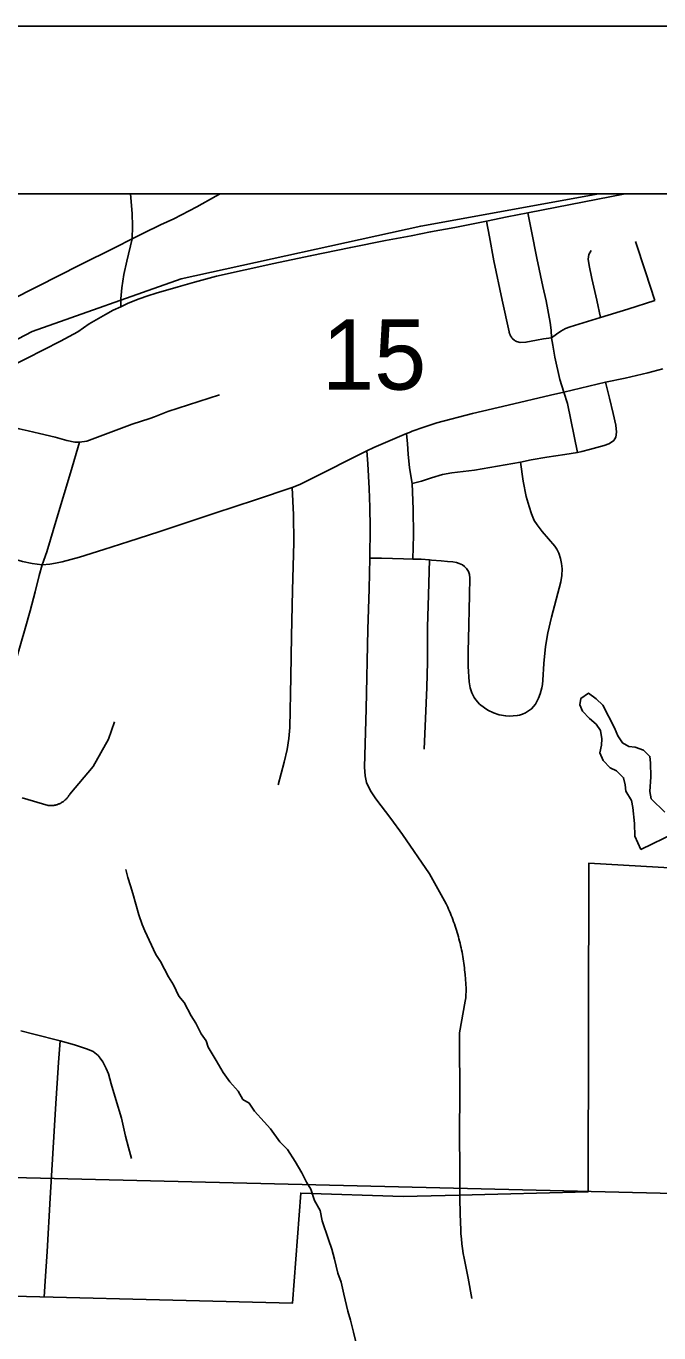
# Model space of a CAD drawing. Extents: x -7.9 to 76.1, y 0 to 22.
# Drawn here: x 2.741 to 3.119, y 20.221 to 21 of the extents above; entities that cross this region are included whole.
import ezdxf

# ---------------------------------------------------------------- set-up
doc = ezdxf.new("R2010")
doc.units = 0
for name, color, linetype in [('GM_X_City_Street', 7, 'Continuous'), ('GM_X_Corporation', 7, 'Continuous'), ('GM_X_County_Road', 7, 'Continuous'), ('GM_X_Minor_River', 7, 'Continuous'), ('GM_X_Rail_Line', 7, 'Continuous'), ('GM_X_Section', 7, 'Continuous'), ('GM_X_Section_Text', 7, 'Continuous'), ('GM_X_State_Route', 7, 'Continuous'), ('GM_X_Township_Road', 7, 'Continuous'), ('SC_Scratch1', 7, 'Continuous'), ('SH_Data', 7, 'Continuous')]:
    doc.layers.add(name, color=color, linetype=linetype)

msp = doc.modelspace()

# ---------------------------------------------------------------- linework, layer by layer
at = {"layer": 'GM_X_City_Street'}
for points in [[(2.73013, 20.79625), (2.74156, 20.80185), (2.7619, 20.81214), (2.77206, 20.81787), (2.77898, 20.82249), (2.78871, 20.82816), (2.79329, 20.83063), (2.79779, 20.83276), (2.80222, 20.8348), (2.80873, 20.83742), (2.81394, 20.83921), (2.81895, 20.84079), (2.83198, 20.84466), (2.8418, 20.84742), (2.85493, 20.8509), (2.872, 20.85477), (2.88912, 20.8585), (2.91073, 20.863), (2.93498, 20.86808), (2.95566, 20.87221), (2.97088, 20.87509), (2.98254, 20.8773), (2.99696, 20.88004), (3.01581, 20.88372), (3.02833, 20.88625), (3.04055, 20.88867), (3.09869, 20.9)], [(2.80456, 20.87327), (2.80467, 20.88085), (2.80448, 20.88825), (2.80361, 20.9)], [(3.03381, 20.81205), (3.03309, 20.81244), (3.03279, 20.81263), (3.03251, 20.81282), (3.03224, 20.81304), (3.03197, 20.81327), (3.03171, 20.8135), (3.03147, 20.81374), (3.03124, 20.81401), (3.03101, 20.81427), (3.0308, 20.81455), (3.0306, 20.81483), (3.03041, 20.81513), (3.03024, 20.81543), (3.03008, 20.81574), (3.02993, 20.81606), (3.0298, 20.81638), (3.02968, 20.81671), (3.02957, 20.81704), (3.02948, 20.81739), (3.0294, 20.81773), (3.02523, 20.83665), (3.02021, 20.86018), (3.0176, 20.8744), (3.01581, 20.88372)], [(3.05469, 20.81422), (3.05443, 20.81869), (3.05387, 20.82338), (3.05152, 20.83625), (3.04956, 20.84478), (3.04599, 20.8616), (3.04284, 20.87774), (3.04055, 20.88867)], [(2.79779, 20.83276), (2.79787, 20.83754), (2.79835, 20.8441), (2.79961, 20.852), (2.8014, 20.85989), (2.80456, 20.87327)], [(3.11628, 20.83642), (3.1107, 20.8536), (3.10487, 20.87156)], [(3.084, 20.82629), (3.08163, 20.83665), (3.07871, 20.8496), (3.07712, 20.85738), (3.07646, 20.86108), (3.07691, 20.86378), (3.07832, 20.86629)], [(3.03381, 20.81205), (3.036, 20.81137), (3.03945, 20.81158), (3.04582, 20.81286), (3.04987, 20.81354), (3.05469, 20.81422), (3.05764, 20.81632), (3.06024, 20.81817), (3.063, 20.81969), (3.06575, 20.82071), (3.084, 20.82629), (3.10017, 20.83137), (3.11628, 20.83642)], [(3.06207, 20.7819), (3.05955, 20.78944), (3.05661, 20.80275), (3.05543, 20.80975), (3.05469, 20.81422)], [(3.03619, 20.74), (3.04255, 20.74138), (3.05195, 20.74297), (3.06263, 20.74471), (3.07016, 20.74594), (3.07283, 20.74651), (3.07734, 20.74755), (3.08618, 20.74997), (3.08882, 20.75099), (3.09056, 20.75196), (3.09191, 20.75309), (3.09297, 20.75493), (3.09353, 20.7579), (3.09311, 20.76207), (3.09148, 20.76914), (3.08922, 20.77826), (3.08683, 20.78768)], [(2.68579, 20.77344), (2.69094, 20.77267), (2.70001, 20.77088), (2.71117, 20.76763), (2.72517, 20.76361), (2.7305, 20.7618), (2.73714, 20.75996), (2.74242, 20.75878), (2.74935, 20.75713), (2.75862, 20.75506), (2.76552, 20.75304), (2.77033, 20.75206), (2.77314, 20.75206), (2.77754, 20.75266), (2.80462, 20.76275), (2.81515, 20.76615), (2.81794, 20.76706), (2.82588, 20.77019), (2.85674, 20.78028)], [(3.07016, 20.74594), (3.06421, 20.77511), (3.06207, 20.7819)], [(2.75092, 20.67896), (2.7536, 20.68657), (2.75964, 20.70676), (2.76784, 20.73381), (2.77314, 20.75206)], [(2.97191, 20.68234), (2.97235, 20.6966), (2.97213, 20.71202), (2.97156, 20.72728), (2.97003, 20.73661), (2.96912, 20.74495), (2.96872, 20.75092), (2.96825, 20.75713)], [(2.99992, 20.31271), (2.99978, 20.34546), (3.00006, 20.35845), (2.99989, 20.39994), (3.00326, 20.41869), (3.00363, 20.42073), (3.00375, 20.42635), (3.00311, 20.43472), (3.00287, 20.43739), (3.00273, 20.43873), (3.00257, 20.44006), (3.00239, 20.44139), (3.0022, 20.44272), (3.002, 20.44405), (3.00178, 20.44537), (3.00155, 20.44669), (3.0013, 20.44801), (3.00104, 20.44933), (3.00076, 20.45065), (3.00047, 20.45195), (3.00016, 20.45326), (2.99984, 20.45457), (2.9995, 20.45587), (2.99915, 20.45716), (2.99879, 20.45846), (2.99841, 20.45974), (2.99802, 20.46102), (2.99761, 20.4623), (2.99718, 20.46358), (2.99675, 20.46485), (2.9963, 20.46612), (2.99584, 20.46737), (2.99536, 20.46863), (2.99486, 20.46988), (2.99436, 20.47113), (2.99383, 20.47236), (2.9933, 20.47359), (2.99275, 20.47482), (2.99219, 20.47604), (2.99188, 20.47671), (2.98197, 20.49474), (2.96577, 20.51817), (2.95885, 20.52768), (2.9499, 20.53948), (2.94711, 20.54352), (2.94545, 20.54656), (2.94442, 20.54918), (2.94359, 20.55317), (2.94322, 20.55832), (2.94419, 20.59304), (2.94522, 20.64031), (2.9459, 20.66453), (2.94632, 20.68294), (2.94651, 20.70108), (2.94631, 20.71323), (2.94588, 20.72448), (2.94507, 20.73909), (2.94453, 20.74675)], [(2.97156, 20.72728), (2.97708, 20.72869), (2.98317, 20.73074), (2.9896, 20.73269), (2.9952, 20.73372), (3.00872, 20.73541), (3.03619, 20.74)], [(2.98182, 20.68179), (2.98307, 20.68168), (2.9888, 20.68119), (2.99268, 20.68091), (2.99587, 20.68065), (2.99797, 20.68022), (2.99965, 20.67971), (3.00151, 20.67884), (3.00288, 20.67783), (3.00395, 20.67676), (3.00513, 20.67494), (3.00571, 20.67321), (3.00606, 20.67099), (3.00584, 20.66109), (3.00514, 20.63431), (3.0049, 20.62779), (3.005, 20.61827), (3.0056, 20.60905), (3.00616, 20.60563), (3.00718, 20.60263), (3.00863, 20.59987), (3.00962, 20.59843), (3.0118, 20.59582), (3.01469, 20.59359), (3.01673, 20.59226), (3.01999, 20.59065), (3.02346, 20.58949), (3.02734, 20.58879), (3.0295, 20.58866), (3.03424, 20.58898), (3.03561, 20.58926), (3.03737, 20.58981), (3.03921, 20.59064), (3.04281, 20.59298), (3.04504, 20.59591), (3.04687, 20.59932), (3.04791, 20.60192), (3.0489, 20.6055), (3.04927, 20.60764), (3.0495, 20.61004), (3.05018, 20.62012), (3.05116, 20.63025), (3.05252, 20.63825), (3.05458, 20.64773), (3.06028, 20.66874), (3.06089, 20.6726), (3.06097, 20.67643), (3.06065, 20.67961), (3.05999, 20.68274), (3.059, 20.68574), (3.05795, 20.68813), (3.05665, 20.69005), (3.04921, 20.69878), (3.04606, 20.70281), (3.04437, 20.70538), (3.0427, 20.70928), (3.04139, 20.7136), (3.03962, 20.7196), (3.0378, 20.72868), (3.03619, 20.74)], [(2.89166, 20.54775), (2.8952, 20.56123), (2.89692, 20.56876), (2.89794, 20.57528), (2.89853, 20.58201), (2.89915, 20.61205), (2.89965, 20.63637), (2.90028, 20.66366), (2.90093, 20.69241), (2.90069, 20.70863), (2.90006, 20.72496)], [(2.94632, 20.68294), (2.9533, 20.68279), (2.9663, 20.68251), (2.97191, 20.68234), (2.97695, 20.6822), (2.98182, 20.68179)], [(2.97879, 20.56906), (2.97954, 20.58722), (2.98031, 20.60578), (2.98067, 20.62104), (2.98079, 20.64174), (2.98136, 20.66109), (2.98182, 20.68179)], [(2.69364, 20.45827), (2.69755, 20.47389), (2.69928, 20.48113), (2.70041, 20.48584), (2.70054, 20.48631), (2.70701, 20.51303), (2.70763, 20.51557), (2.71021, 20.52511), (2.71248, 20.53348), (2.71609, 20.54779), (2.71682, 20.55071), (2.72258, 20.57232), (2.72935, 20.59979), (2.73054, 20.60417), (2.73562, 20.62311), (2.74072, 20.64098), (2.74371, 20.65146), (2.74661, 20.66275), (2.74903, 20.67255), (2.75092, 20.67896)], [(2.73891, 20.54007), (2.75438, 20.53541), (2.75789, 20.53549), (2.75832, 20.53557), (2.75875, 20.53566), (2.75918, 20.53577), (2.7596, 20.53589), (2.76003, 20.53602), (2.76044, 20.53617), (2.76085, 20.53634), (2.76126, 20.53651), (2.76165, 20.53671), (2.76205, 20.53691), (2.76244, 20.53713), (2.76282, 20.53737), (2.76318, 20.53761), (2.76355, 20.53786), (2.7639, 20.53813), (2.76424, 20.53842), (2.76458, 20.53871), (2.7649, 20.53901), (2.76522, 20.53932), (2.76552, 20.53965), (2.76582, 20.53998), (2.7661, 20.54032), (2.76637, 20.54068), (2.76662, 20.54104), (2.76687, 20.54141), (2.76711, 20.54179), (2.7673, 20.54213), (2.78133, 20.5587), (2.79045, 20.57506), (2.79403, 20.58538)], [(2.80407, 20.32507), (2.80239, 20.33159), (2.80064, 20.33824), (2.79819, 20.3491), (2.79479, 20.36016), (2.79201, 20.36942), (2.79035, 20.37541), (2.78901, 20.37867), (2.78697, 20.38271), (2.78548, 20.38476), (2.78421, 20.38645), (2.78123, 20.38873), (2.7779, 20.39019), (2.77019, 20.39281), (2.76165, 20.3952), (2.74595, 20.39908), (2.73805, 20.40109)], [(2.75203, 20.24249), (2.75259, 20.25183), (2.75391, 20.26949), (2.75558, 20.30139), (2.75881, 20.35453), (2.76054, 20.38225), (2.76165, 20.3952)]]:
    msp.add_lwpolyline(points, dxfattribs=at)
at = {"layer": 'GM_X_Corporation'}
msp.add_lwpolyline([(3.73705, 20.9), (2.1, 20.9), (2.1, 20.32547), (2.13909, 20.3247), (2.11815, 20.27512), (2.1, 20.24182), (2.1, 20.11437), (2.11627, 20.09137), (2.18176, 20.10791), (2.41814, 20.16758), (2.62296, 20.20833), (2.6405, 20.17691), (2.64749, 20.18312), (2.67775, 20.21), (2.67792, 20.24438), (2.90025, 20.23882), (2.90507, 20.30438), (2.96613, 20.30239), (2.9996, 20.30322), (3.07654, 20.30512), (3.07694, 20.50096), (3.40799, 20.48207)], dxfattribs=at)
at = {"layer": 'GM_X_County_Road'}
for p, q in [((3.08683, 20.78768), (3.06207, 20.7819)), ((2.96993, 20.75783), (2.96825, 20.75713))]:
    msp.add_line(p, q, dxfattribs=at)
for points in [[(2.67414, 20.80187), (2.67784, 20.8047), (2.68234, 20.80744), (2.69037, 20.81298), (2.69977, 20.81878), (2.71832, 20.82974), (2.73162, 20.83655), (2.74841, 20.84507), (2.77319, 20.85758), (2.79434, 20.868), (2.80456, 20.87327), (2.81139, 20.87666), (2.82152, 20.8815), (2.82943, 20.88523), (2.84319, 20.89225), (2.85454, 20.89866), (2.85699, 20.9)], [(3.12118, 20.79564), (3.11213, 20.79336), (3.09867, 20.79022), (3.08683, 20.78768)], [(3.06207, 20.7819), (3.05406, 20.78001), (3.02881, 20.77404), (3.00753, 20.76904), (2.98635, 20.76356), (2.97849, 20.76103), (2.97162, 20.75854), (2.96993, 20.75783)], [(2.96825, 20.75713), (2.96118, 20.75418), (2.94866, 20.74873), (2.94453, 20.74675)], [(2.94453, 20.74675), (2.94007, 20.7446), (2.92908, 20.73913), (2.92556, 20.73726)], [(2.92556, 20.73726), (2.91736, 20.7331), (2.90979, 20.72926), (2.90451, 20.72677), (2.90006, 20.72496)], [(2.90006, 20.72496), (2.87814, 20.71758), (2.85393, 20.70976), (2.82045, 20.69859), (2.80256, 20.69281), (2.78771, 20.68811), (2.77307, 20.68349), (2.76288, 20.68066), (2.7588, 20.67985), (2.75535, 20.67925), (2.75092, 20.67896)], [(2.75092, 20.67896), (2.74488, 20.67971), (2.73913, 20.68095), (2.6978, 20.69273), (2.69298, 20.6941)]]:
    msp.add_lwpolyline(points, dxfattribs=at)
at = {"layer": 'GM_X_Minor_River'}
for points in [[(3.10788, 20.50927), (3.10434, 20.51717), (3.10421, 20.52475), (3.10329, 20.53421), (3.10246, 20.53836), (3.09896, 20.54399), (3.09852, 20.54777), (3.09769, 20.55193), (3.09345, 20.55602), (3.08964, 20.55785), (3.0854, 20.56232), (3.08343, 20.56684), (3.08448, 20.5714), (3.0848, 20.5752), (3.08395, 20.58011), (3.08124, 20.58386), (3.0774, 20.5872), (3.07316, 20.59167), (3.07158, 20.59544), (3.07227, 20.59924), (3.07676, 20.60235), (3.08136, 20.59902), (3.08521, 20.5953), (3.09225, 20.58178), (3.09423, 20.57688), (3.09695, 20.57276), (3.10077, 20.57055), (3.10456, 20.57024), (3.10951, 20.56844), (3.11336, 20.56471), (3.1138, 20.56093), (3.11395, 20.55259), (3.11334, 20.54386), (3.11417, 20.53933), (3.12226, 20.53151)], [(3.12853, 20.51911), (3.10788, 20.50927)], [(2.80083, 20.49737), (2.80205, 20.49247), (2.80365, 20.48757), (2.80486, 20.48304), (2.80848, 20.47022), (2.81048, 20.46457), (2.81205, 20.46081), (2.81873, 20.44652), (2.82145, 20.4424), (2.82615, 20.43338), (2.82926, 20.42851), (2.83241, 20.42174), (2.8355, 20.41801), (2.8398, 20.41012), (2.84252, 20.40562), (2.84566, 20.39923), (2.84876, 20.39512), (2.84996, 20.39135), (2.85464, 20.38347), (2.85892, 20.37634), (2.8628, 20.37073), (2.86782, 20.36513), (2.87055, 20.36025), (2.87437, 20.35804), (2.87748, 20.35317), (2.88327, 20.34683), (2.88713, 20.34273), (2.89256, 20.33486), (2.89718, 20.3304), (2.90184, 20.32328), (2.90574, 20.31652), (2.90849, 20.31089), (2.91121, 20.30676), (2.91322, 20.29998), (2.91673, 20.29397), (2.91797, 20.28793), (2.92157, 20.27662), (2.92356, 20.27097), (2.92518, 20.26493), (2.92721, 20.25663), (2.9292, 20.25136), (2.93083, 20.24418), (2.93328, 20.23399), (2.93488, 20.22871), (2.93652, 20.22154), (2.93937, 20.21022)]]:
    msp.add_lwpolyline(points, dxfattribs=at)
at = {"layer": 'GM_X_Rail_Line'}
msp.add_lwpolyline([(2.1, 20.24354), (2.10641, 20.25873), (2.14272, 20.31539), (2.18204, 20.36346), (2.25833, 20.43461), (2.39668, 20.55564), (2.51835, 20.66438), (2.60263, 20.73145), (2.66693, 20.77716), (2.74484, 20.81794), (2.83376, 20.8494), (2.97671, 20.88078), (3.08282, 20.9)], dxfattribs=at)
at = {"layer": 'GM_X_Section'}
msp.add_lwpolyline([(3.44816, 20.29633), (3.41682, 19.27112), (2.40571, 19.29621), (2.42909, 20.32093)], close=True, dxfattribs=at)
at = {"layer": 'GM_X_State_Route'}
for p, q in [((3.06207, 20.7819), (3.08683, 20.78768)), ((2.96825, 20.75713), (2.96993, 20.75783))]:
    msp.add_line(p, q, dxfattribs=at)
for points in [[(3.08683, 20.78768), (3.09867, 20.79022), (3.11213, 20.79336), (3.12118, 20.79564)], [(2.96993, 20.75783), (2.97162, 20.75854), (2.97849, 20.76103), (2.98635, 20.76356), (3.00753, 20.76904), (3.02881, 20.77404), (3.05406, 20.78001), (3.06207, 20.7819)], [(2.94453, 20.74675), (2.94866, 20.74873), (2.96118, 20.75418), (2.96825, 20.75713)], [(2.92556, 20.73726), (2.92908, 20.73913), (2.94007, 20.7446), (2.94453, 20.74675)], [(2.90006, 20.72496), (2.90451, 20.72677), (2.90979, 20.72926), (2.91736, 20.7331), (2.92556, 20.73726)], [(2.75092, 20.67896), (2.75535, 20.67925), (2.7588, 20.67985), (2.76288, 20.68066), (2.77307, 20.68349), (2.78771, 20.68811), (2.80256, 20.69281), (2.82045, 20.69859), (2.85393, 20.70976), (2.87814, 20.71758), (2.90006, 20.72496)], [(2.69298, 20.6941), (2.6978, 20.69273), (2.73913, 20.68095), (2.74488, 20.67971), (2.75092, 20.67896)]]:
    msp.add_lwpolyline(points, dxfattribs=at)
at = {"layer": 'GM_X_Township_Road'}
msp.add_lwpolyline([(3.00725, 20.24155), (3.00488, 20.2536), (3.0031, 20.26262), (3.00255, 20.2655), (3.00206, 20.26839), (3.00163, 20.27129), (3.00126, 20.2742), (3.00094, 20.27712), (3.00069, 20.28004), (3.00052, 20.28255), (3.0002, 20.29188), (3.00007, 20.30164), (2.99992, 20.31271)], dxfattribs=at)
at = {"layer": 'SC_Scratch1'}
msp.add_lwpolyline([(3.46409, 20.9), (2.43893, 20.9), (2.42909, 20.32093), (3.44816, 20.29633)], close=True, dxfattribs=at)
at = {"layer": 'SH_Data'}
for p, q in [((2, 21), (9, 21)), ((2.1, 20.9), (8.9, 20.9))]:
    msp.add_line(p, q, dxfattribs=at)

# ---------------------------------------------------------------- texts
at = {"layer": 'GM_X_Section_Text'}
msp.add_text('15', height=0.041856, rotation=0.00001, dxfattribs=at).set_placement((2.91774, 20.78332))

doc.saveas('drawing.dxf')
